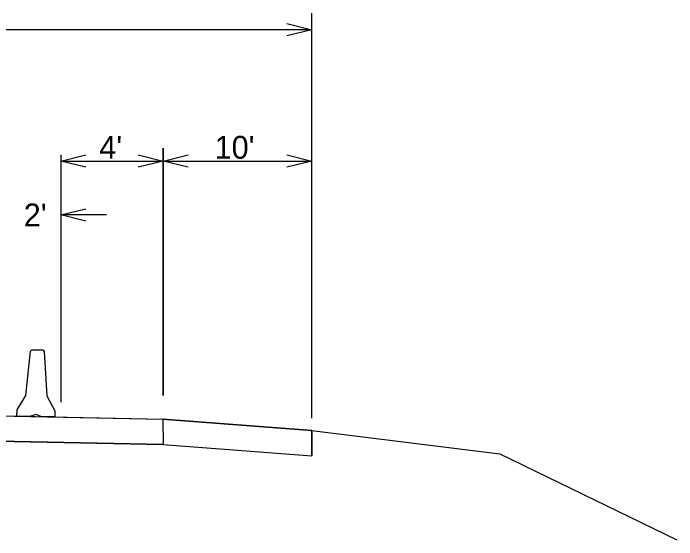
# Model space of a CAD drawing. Extents: x 10133 to 81668, y 4856 to 11018.
# Drawn here: x 10988.5 to 11423.1, y 5358.2 to 5702.8 of the extents above; entities that cross this region are included whole.
import ezdxf

# ---------------------------------------------------------------- set-up
doc = ezdxf.new("R2010")
doc.units = 0
for name, color, linetype in [('dsnXsPCCPavement', 7, 'Continuous'), ('dsnXsPCCPavementBottom', 7, 'Continuous'), ('dsnXsShldrEarthFill', 7, 'Continuous'), ('dsnXsShldrGranular', 7, 'Continuous'), ('dsnXsShldrGranularBottom', 7, 'Continuous'), ('dsnXsShldrSpecialBackBottom', 7, 'Continuous')]:
    doc.layers.add(name, color=color, linetype=linetype)

msp = doc.modelspace()

# ---------------------------------------------------------------- linework, layer by layer
at = {"layer": 'dsnXsPCCPavement'}
msp.add_lwpolyline([(10990.93, 5443.21), (10996.65, 5452.65), (10999.66, 5481.62), (11000.6, 5482.62), (11007.77, 5482.47), (11008.66, 5481.43), (11010.44, 5452.36), (11015.76, 5442.68), (11015.67, 5438.58), (11007.12, 5438.77), (11003.28, 5440.21), (10999.39, 5438.93), (10990.84, 5439.11)], close=True, dxfattribs=at)
at = {"layer": 'dsnXsPCCPavementBottom'}
for p, q in [((11183.99, 5437.71), (11183.99, 5702.81)), ((11184.03, 5692.07), (10591.83, 5692.07)), ((11086.58, 5452.57), (11086.58, 5614.44)), ((11086.58, 5614.44), (11086.58, 5452.57)), ((11086.58, 5614.44), (11086.58, 5452.57)), ((11019.58, 5610.22), (11019.58, 5448.35)), ((11019.58, 5606.12), (11086.58, 5606.12)), ((11086.58, 5606.12), (11183.99, 5606.12)), ((11049.48, 5570.8), (11019.58, 5570.8))]:
    msp.add_line(p, q, dxfattribs=at)
for points in [[(11167.64, 5696.17), (11184.03, 5692.07), (11167.64, 5687.97)], [(11035.97, 5602.02), (11019.58, 5606.12), (11035.97, 5610.22)], [(11070.19, 5610.22), (11086.58, 5606.12), (11070.19, 5602.02)], [(11102.97, 5602.02), (11086.58, 5606.12), (11102.97, 5610.22)], [(11167.6, 5610.22), (11183.99, 5606.12), (11167.6, 5602.02)], [(11035.97, 5566.7), (11019.58, 5570.8), (11035.97, 5574.89)]]:
    msp.add_lwpolyline(points, dxfattribs=at)
at = {"layer": 'dsnXsShldrGranular'}
msp.add_line((11086.58, 5420.52), (10887.56, 5424.75), dxfattribs=at)
msp.add_lwpolyline([(10887.91, 5441.3), (11086.34, 5437.08), (11086.58, 5420.52)], dxfattribs=at)
msp.add_lwpolyline([(11183.99, 5429.81), (11086.34, 5437.08), (11086.58, 5420.52), (11183.99, 5413.21)], close=True, dxfattribs=at)
at = {"layer": 'dsnXsShldrGranularBottom'}
for p, q in [((10887.91, 5441.3), (11086.34, 5437.08)), ((11086.34, 5437.08), (11086.58, 5420.52)), ((11086.34, 5437.08), (11086.58, 5420.52)), ((11086.34, 5437.08), (11086.58, 5420.52)), ((11086.34, 5437.08), (11086.58, 5420.52)), ((11183.99, 5429.81), (11307.1, 5414.34)), ((10887.56, 5424.75), (11086.58, 5420.52)), ((11307.1, 5414.34), (11423.08, 5358.23))]:
    msp.add_line(p, q, dxfattribs=at)
at = {"layer": 'dsnXsShldrSpecialBackBottom'}
for p, q in [((11086.34, 5437.08), (11183.99, 5429.81)), ((11183.99, 5429.81), (11183.99, 5413.21)), ((11086.58, 5420.52), (11183.99, 5413.21))]:
    msp.add_line(p, q, dxfattribs=at)

# ---------------------------------------------------------------- texts
at = {"layer": 'dsnXsShldrEarthFill'}
for s, p in [("4'", (11044.81, 5607.59)), ("2'", (10995.33, 5563.27))]:
    msp.add_text(s, height=15, dxfattribs=at).set_placement(p)
msp.add_text("10'", height=15, rotation=0, dxfattribs=at).set_placement((11120.36, 5607.59))

doc.saveas('drawing.dxf')
